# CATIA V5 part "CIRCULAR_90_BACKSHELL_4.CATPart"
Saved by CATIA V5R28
Part number: CIRCULAR_90_BACKSHELL_4
Revision: --A
Publications: "Logical Termination.1", "BCP", "BCPRPoint_generated(BCP)", "BCPPlane_generated(BCP)", "BaCP", "Face_generated(BaCP)", "Face_generated(BaCP).1", "MasterKeywayAxis", "Axis_generated(BaCP)"
Bounding box of the stored display mesh (mm): x 0 to 43.612, y -13.041 to 13.041, z -45.72 to 12.972
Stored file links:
  C:\Users\ajc8720\Documents\BOEING_WORK\0001-2CES\004-AP242\Boeing-Generic_Harness_R3\CIRCULAR_90_BACKSHELL_4.CATPart
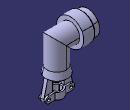
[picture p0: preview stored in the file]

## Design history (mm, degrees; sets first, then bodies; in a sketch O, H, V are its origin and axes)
Parameters
  PartNumber = "CIRCULAR_90_BACKSHELL_4"
AxisSystem1 "MasterKeywayAxis": origin (0, 0, 0), X (1, 0, 0), Y (0, 1, 0), Z (0, 0, 1)
Set1
  Point1: (29.7434 {= Sketch2.distance(P3 V)}, 12.7, 0)
  Plane1: type 1Line1Pt, RefPoint Point1, Line Sketch2.L1
  Point2: type OnCurve, Support Sketch2.L4, Ratio 0.5
  Line1: type PtDir, RefPoint Point2, Direction (0, 1, 0), Start 0, End 5.08
  Point3: type OnCurve, Support Line1, Ratio 0.5
  Plane2: type 1Line1Pt, RefPoint Point3, Line Sketch2.L4
  Point4: type Center, Curve edge [face of Shaft1 from Sketch1.L5 | face of Shaft1 from Sketch1.L6]
  Plane3: type Tangent, Support face of Shaft1 from Sketch1.L5, RefPoint Point4
  Plane4: type OffsetPt, RefPlane Plane2, RefPoint Sketch2.P10
  Line2: type PtPt, FirstPoint vertex [face of Pad3 from Sketch5.L6 | face of Pad3 from Sketch5.L12 | end face of Pad3], SecondPoint vertex [face of Pad3 from Sketch5.L3 | face of Pad3 from Sketch5.L4 | start face of Pad3]
  Point5: type OnCurve, Support Line2, Ratio 0.5
  Plane5: type Tangent, Support face of Pad3 from Sketch5.L6, RefPoint Point5
Set2 "EGF"
  Set3 "BCP"
    Point6 "BCPRPoint": type Center, Curve edge [start face of Pad4 | face of Pad4 from Sketch6.A3]
    Plane6 "BCPPlane": type Tangent, Support start face of Pad4, RefPoint Point6
  Set4 "BaCP"
    Point7 "BaCPRPoint": type Center, Curve edge [face of Shaft1 from Sketch1.L6 | face of Shaft1 from Sketch1.L7]
    Plane7 "BaCPCPlane": type Tangent, Support face of Shaft1 from Sketch1.L7, RefPoint Point7
    Line3 "BaCPCLine": type PtDir, RefPoint Point7, Direction (0, 1, 0), Start 0, End 5.08
Body1 (main body)
  Sketch1 on xy-plane, origin (0, 0, 0), H (1, 0, 0), V (0, 1, 0)
    line L1 (0, 8.7249) -> (0, 11.43)
    line L2 (0, 11.43) -> (4.7625, 11.43)
    point P3 (4.7625, 11.43)
    line L3 (4.7625, 11.43) -> (6.3754, 13.0429)
    line L4 (6.3754, 13.0429) -> (16.764, 13.0429)
    line L5 (16.764, 13.0429) -> (16.764, 5.6896)
    line L6 (16.764, 5.6896) -> (7.747, 5.6896)
    line L7 (7.747, 5.6896) -> (7.747, 8.7249)
    line L8 (7.747, 8.7249) -> (0, 8.7249)
    axis line L9 (-2.2417, 0) -> (20.7737, 0)
    point P9 (-2.2417, 0)
    distance P3 L1 = 4.7625
    angle L3 L4 = 45
    distance L1 L7 = 7.747
    distance L1 L5 = 16.764
    distance L6 H = 5.6896
    distance L8 H = 8.7249
    distance L2 H = 11.43
    distance L4 H = 13.0429
    vertical: L1 V, L5 V, L7 V
    horizontal: L2 H, L4 H, L6 H, L8 H, L9 H
    coincidence: L1 V, P9 H
  Shaft1: profile Sketch1, axis Sketch1.L9, angle 360
  Sketch2 on zx-plane, origin (0, 0, 0), H (-1, 0, 0), V (0, 0, 1)
    line L1 (-29.7434, 0) -> (-47.8252, 18.0818)
    line L2 (-29.7434, 0) -> (-36.5055, 0)
    point P3 (-29.7434, 0)
    line L3 (-29.7434, 0) -> (-29.7434, -20.32)
    line L4 (-29.7434, -20.32) -> (64.1804, -20.32)
    reference projected point E1 (-29.7434, 0) from Point1
    point P7 (-29.7434, -20.32)
    line L5 (-29.7434, -26.67) -> (64.1804, -26.67)
    construction line L6 (-29.7434, -20.32) -> (-29.7434, -26.67)
    construction line L7 (64.1804, -20.32) -> (64.1804, -26.67)
    point P10 (-29.7434, -26.67)
    point P11 (-29.7434, 0)
    angle L1 V = 45
    distance P3 V = 29.7434
    distance L4 E1 = 20.32
    angle L3 H = 90
    distance L4 L5 = 6.35
    horizontal: L2 H
    coincidence: L2 P3, L1 P3, L2 H, L4 P7, L3 P7, L3 P10, L5 P10, L1 P11, L3 P11
    perpendicularity: L4 L3, L6 L4, L6 L5, L7 L4, L7 L5
  Sketch3 on Plane3, origin (16.764, 0, 0), H (0, -1, 0), V (0, 0, 1)
    circle A1 centre (0, 0) radius 5.6896
    circle A2 centre (0, 0) radius 9.1186
    radius A1 = 5.6896
    radius A2 = 9.1186
  Pad1: profile Sketch3, direction (1, 0, 0), up to Plane1
  Sketch4 on Plane2, origin (-94.0894, 0, -20.32), H (0, 1, 0), V (1, 0, 0)
    circle A1 centre (0, 123.8328) radius 5.6896
    point P1 (0, 123.8328)
    circle A2 centre (0, 123.8328) radius 9.1186
    reference projected point E1 (0, 123.8328) from Sketch2.P7
    radius A1 = 5.6896
    radius A2 = 9.1186
    coincidence: P1 V, P1 E1
  Pad2: profile Sketch4, direction (0, 0, 1), up to Plane1
  Sketch5 on zx-plane, origin (0, 0, 0), H (-1, 0, 0), V (0, 0, 1)
    point P1 (0, 0)
    construction line L1 (0, 0) -> (-29.7434, 0)
    point P2 (-29.7434, 0)
    construction line L2 (-29.7434, 0) -> (-29.7434, -26.67)
    point P3 (-29.7434, -26.67)
    point P4 (6.6487, -26.67)
    line L3 (-40.4368, -45.72) -> (-33.7058, -45.72)
    point P5 (-33.7058, -45.72)
    line L4 (-33.7058, -45.72) -> (-33.7058, -39.37)
    line L5 (-35.433, -26.67) -> (-40.2402, -26.67)
    circle A1 centre (-40.4368, -42.545) radius 1.8256
    arc A2 centre (-40.4368, -42.545) radius 3.175 from (-40.4368, -45.72) to (-43.5396, -41.8716) cw
    point P7 (-40.4368, -45.72)
    point P8 (-43.5396, -41.8716)
    point P10 (-25.781, -45.72)
    point P12 (-19.05, -45.72)
    line L6 (-19.05, -45.72) -> (-25.781, -45.72)
    circle A3 centre (-19.05, -42.545) radius 1.8256
    line L7 (-43.5396, -41.8716) -> (-40.2402, -26.67)
    point P13 (-43.5396, -41.8716)
    point P14 (-40.2402, -26.67)
    point P15 (-15.9472, -41.8716)
    point P16 (-19.05, -45.72)
    arc A4 centre (-19.05, -42.545) radius 3.175 from (-19.05, -45.72) to (-15.9472, -41.8716) ccw
    point P18 (-19.2466, -26.67)
    point P19 (-15.9472, -41.8716)
    line L8 (-15.9472, -41.8716) -> (-19.2466, -26.67)
    construction line L9 (-38.862, -20.32) -> (-52.8711, -84.8662)
    point P20 (-38.862, -20.32)
    line L10 (-33.7058, -39.37) -> (-35.433, -39.37)
    line L11 (-35.433, -39.37) -> (-35.433, -26.67)
    point P22 (-33.7058, -39.37)
    point P23 (-35.433, -26.67)
    point P24 (-35.433, -39.37)
    point P25 (-25.781, -39.37)
    point P26 (-25.781, -45.72)
    line L12 (-25.781, -45.72) -> (-25.781, -39.37)
    point P27 (-24.0538, -39.37)
    point P28 (-25.781, -39.37)
    line L13 (-25.781, -39.37) -> (-24.0538, -39.37)
    point P29 (-24.0538, -26.67)
    point P30 (-24.0538, -39.37)
    line L14 (-24.0538, -39.37) -> (-24.0538, -26.67)
    point P31 (-19.2466, -26.67)
    point P32 (-24.0538, -26.67)
    line L15 (-24.0538, -26.67) -> (-19.2466, -26.67)
    distance P1 P2 = 29.7434
    angle L1 L2 = 90
    distance P3 P2 = 26.67
    distance L5 L3 = 19.05
    radius A1 = 1.8256
    radius A2 = 3.175
    distance L4 L2 = 3.9624
    distance A2 L2 = 13.8684
    distance P20 L2 = 9.1186 {= Sketch3.radius(A2)}
    distance P20 L5 = 6.35
    distance L10 L3 = 6.35
    distance L11 L2 = 5.6896
    horizontal: L1 H
    coincidence: P1 O, L5 P3, L7 P8, P8 A2, P4 L5, L7 L9
    tangency: A2 L3, A2 L7, L9 A2
    concentricity: A1 A2
    symmetry: P5 P10 L2, P7 P12 L2, L3 L6 L2, A1 A3 L2, P13 P15 L2, P7 P16 L2, A2 A4 L2, P14 P18 L2, P13 P19 L2, L7 L8 L2, P22 P25 L2, P5 P26 L2, L4 L12 L2, P24 P27 L2, P22 P28 L2, L10 L13 L2, P23 P29 L2, P24 P30 L2, L11 L14 L2, P14 P31 L2, P23 P32 L2, L5 L15 L2
    parallelism: L4 L2, L3 L5, L11 L4
    perpendicularity: L3 L2
  Pad3: profile Sketch5, direction (0, 1, 0), length 1.5875, opposite side length 1.5875
  Sketch6 on Plane5, origin (-177.0727, 0, -45.72), H (0, -1, 0), V (1, 0, 0)
    arc A1 centre (0, 206.8161) radius 4.3024 from (1.6764, 210.7785) to (1.6764, 202.8537) cw
    point P1 (0, 206.8161)
    point P2 (1.6764, 210.7785)
    line L1 (1.6764, 210.7785) -> (1.6764, 220.6845)
    point P3 (1.6764, 220.6845)
    line L2 (1.6764, 192.9477) -> (1.6764, 202.8537)
    point P4 (1.6764, 192.9477)
    point P5 (1.6764, 202.8537)
    line L3 (3.2639, 192.9477) -> (3.2639, 201.9132)
    point P6 (3.2639, 192.9477)
    point P7 (3.2639, 201.9132)
    arc A2 centre (0, 206.8161) radius 5.8899 from (3.2639, 201.9132) to (3.2639, 211.719) ccw
    point P8 (3.2639, 211.719)
    line L4 (3.2639, 211.719) -> (3.2639, 220.6845)
    point P9 (3.2639, 220.6845)
    line L5 (1.6764, 192.9477) -> (3.2639, 192.9477)
    line L6 (1.6764, 220.6845) -> (3.2639, 220.6845)
    construction line L7 (0, 206.8161) -> (0, 27.9514)
    point P11 (-1.6764, 210.7785)
    point P12 (-1.6764, 220.6845)
    point P13 (-1.6764, 192.9477)
    point P14 (-1.6764, 202.8537)
    point P15 (-3.2639, 192.9477)
    point P16 (-3.2639, 201.9132)
    point P17 (-3.2639, 211.719)
    point P18 (-3.2639, 220.6845)
    point P19 (0, 206.8161)
    arc A3 centre (0, 206.8161) radius 4.3024 from (-1.6764, 210.7785) to (-1.6764, 202.8537) ccw
    line L8 (-1.6764, 210.7785) -> (-1.6764, 220.6845)
    line L9 (-1.6764, 192.9477) -> (-1.6764, 202.8537)
    line L10 (-3.2639, 192.9477) -> (-3.2639, 201.9132)
    arc A4 centre (0, 206.8161) radius 5.8899 from (-3.2639, 201.9132) to (-3.2639, 211.719) cw
    line L11 (-3.2639, 211.719) -> (-3.2639, 220.6845)
    line L12 (-1.6764, 192.9477) -> (-3.2639, 192.9477)
    line L13 (-1.6764, 220.6845) -> (-3.2639, 220.6845)
    reference projected point E1 (0, 206.8161) from Point5
    distance L2 L3 = 1.5875
    distance L2 P1 = 1.6764
    distance A1 A2 H = 1.5875
    distance L5 P1 = 13.8684
    distance L6 P1 = 13.8684
    distance P5 P19 V = 3.9624
    vertical: L1 V, L2 V, L7 V
    coincidence: P4 L1, L2 L1, L3 L4, P19 E1
    concentricity: A2 A1
    horizontal: L5 H, L6 H
    symmetry: P2 P11 L7, P3 P12 L7, P4 P13 L7, P5 P14 L7, P6 P15 L7, P7 P16 L7, P8 P17 L7, P9 P18 L7, A1 A3 L7, L1 L8 L7, L2 L9 L7, L3 L10 L7, A2 A4 L7, L4 L11 L7, L5 L12 L7, L6 L13 L7
  Pad4: profile Sketch6, direction (0, 0, 1), length 6.35
  Fillet1: radius 3.175 {= deleted_StrainReleaseWidth /2}, on edge [start face of Pad4 | face of Pad4 from Sketch6.L13]; edge [face of Pad4 from Sketch6.L13 | end face of Pad4]; edge [start face of Pad4 | face of Pad4 from Sketch6.L6]; edge [face of Pad4 from Sketch6.L6 | end face of Pad4]; edge [start face of Pad4 | face of Pad4 from Sketch6.L12]; edge [start face of Pad4 | face of Pad4 from Sketch6.L5]; edge [face of Pad4 from Sketch6.L12 | end face of Pad4]; edge [face of Pad4 from Sketch6.L5 | end face of Pad4]
  Sketch7 on face of Pad4 from Sketch6.L11, origin (72.7908, 3.2639, -31.7287), H (1, 0, 0), V (0, 0, -1)
    point P1 (-32.354, 10.8163)
    reference projected arc E1 centre (-32.354, 10.8163) radius 3.175 from (-30.1089, 8.5712) to (-30.1089, 13.0613) ccw from edge [face of Pad4 from Sketch6.L11 | face of Fillet1]
    concentricity: P1 E1
  Hole1: placed by Sketch7, at (40.4368, 3.2639, -42.545) direction (0, -1, 0), diameter 3.175, up to face of Pad4 from Sketch6.L4
  Sketch8 on face of Pad4 from Sketch6.L10, origin (57.6407, 3.2639, -47.0401), H (1, 0, 0), V (0, 0, -1)
    point P1 (-38.5907, -4.4951)
    reference projected arc E1 centre (-38.5907, -4.4951) radius 3.175 from (-36.3456, -2.2501) to (-40.8357, -2.2501) ccw from edge [face of Pad4 from Sketch6.L10 | face of Fillet1]
    concentricity: P1 E1
  Hole2: placed by Sketch8, at (19.05, 3.2639, -42.545) direction (0, -1, 0), diameter 3.175, up to face of Pad4 from Sketch6.L3
  Sketch9 on zx-plane, origin (0, 0, 0), H (-1, 0, 0), V (0, 0, 1)
    construction line L1 (-24.3125, 0) -> (-29.7434, 0)
    point P1 (-24.3125, 0)
    point P2 (-29.7434, 0)
    construction line L2 (-29.7434, 0) -> (-29.7434, -20.32)
    point P3 (-29.7434, -20.32)
    construction line L3 (-29.7434, -20.32) -> (-0.0419, -20.32)
    line L4 (-40.2402, -26.67) -> (-38.862, -20.32)
    point P6 (-38.862, -20.32)
    line L5 (-38.862, -20.32) -> (-35.433, -20.32)
    line L6 (-35.433, -20.32) -> (-35.433, -26.67)
    line L7 (-35.433, -26.67) -> (-40.2402, -26.67)
    axis line L8 (-29.7434, -20.32) -> (-29.7434, -102.2456)
    reference projected point E1 (-40.2402, -26.67) from edge [face of Pad3 from Sketch5.L7 | face of Pad3 from Sketch5.L5]
    distance P2 V = 29.7434
    angle L1 L2 = 90
    distance P2 P3 = 20.32
    distance P6 L2 = 9.1186
    distance L5 L7 = 6.35
    distance L6 L2 = 5.6896
    coincidence: P1 H, L5 L3, L4 E1
    horizontal: L1 H
    perpendicularity: L3 L2
    parallelism: L8 L2
  Shaft2: profile Sketch9, axis Sketch9.L8, angle 360
Body2 "BaCP"
  Sketch10 "Sketch" on Plane7, origin (7.747, 0, 0), H (0, 1, 0), V (0, 0, 1)
    line L1 (-0.672, 0.762) -> (0.672, 0.762)
    point P1 (-0.672, 0.762)
    point P2 (0.672, 0.762)
    arc A1 centre (0, 0) radius 1.016 from (-1.016, 0) to (1.016, 0) ccw
    point P3 (0, 0)
    point P4 (-1.016, 0)
    point P5 (1.016, 0)
    reference projected point E1 (0, 0) from Point7
    arc A2 centre (0, 0) radius 1.016 from (1.016, 0) to (0.672, 0.762) ccw
    point P6 (0, 0)
    point P7 (1.016, 0)
    point P8 (0.672, 0.762)
    arc A3 centre (0, 0) radius 1.016 from (-0.672, 0.762) to (-1.016, 0) ccw
    point P9 (0, 0)
    point P10 (-0.672, 0.762)
    point P11 (-1.016, 0)
    reference projected point E2 (0, 0) from Point7
    reference projected point E3 (0, 0) from Point7
    length L1 = 1.344
    radius A1 = 1.016
    radius A3 = 1.016
    radius A2 = 1.016
    distance L1 P5 = 0.762
    distance P4 L1 = 0.762
    distance P7 L1 = 0.762
    distance P11 L1 = 0.762
    coincidence: P3 E1, P6 E2, P9 E3, P8 P2, P10 P1
    horizontal: L1 H
  Pad5: profile Sketch10, direction (1, 0, 0), length 0.508, opposite side up to Plane7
